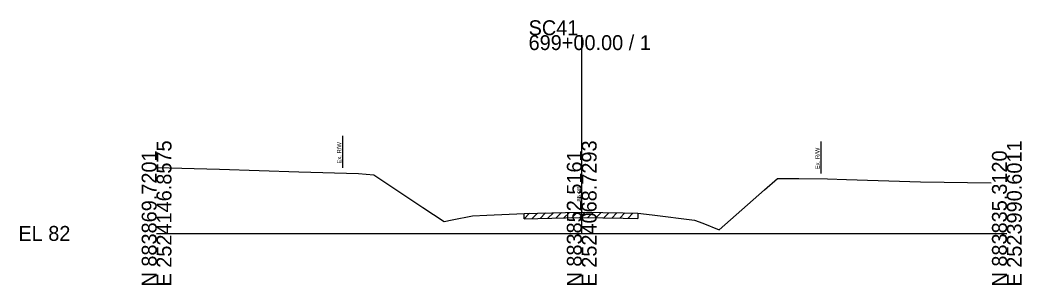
# Model space of a CAD drawing. Extents: x -26 to 183, y -10 to 24021.
# Drawn here: x -25.7 to 162.8, y 21490.3 to 21540.1 of the extents above; entities that cross this region are included whole.
import ezdxf

# ---------------------------------------------------------------- set-up
doc = ezdxf.new("R2010")
doc.units = 0
for name, color, linetype in [('RD_GPK_XS_Cell', 7, 'Continuous'), ('RD_XS_ExGround', 7, 'Continuous'), ('RD_XS_ExPaveRet', 7, 'Continuous'), ('RD_XS_ExRW', 7, 'Continuous'), ('RD_XS_TX_Elev_EX', 7, 'Continuous')]:
    doc.layers.add(name, color=color, linetype=linetype)

msp = doc.modelspace()

# ---------------------------------------------------------------- linework, layer by layer
at = {"layer": 'RD_GPK_XS_Cell'}
for p, q in [((80, 21500), (80, 21537.27)), ((0, 21500), (80, 21500)), ((80, 21500), (160, 21500))]:
    msp.add_line(p, q, dxfattribs=at)
at = {"layer": 'RD_XS_ExGround'}
for p, q in [((0, 21512.42), (11.84, 21512.08)), ((11.84, 21512.08), (26.78, 21511.55)), ((26.78, 21511.55), (37.98, 21511.25)), ((37.98, 21511.25), (40.86, 21511.04)), ((40.86, 21511.04), (50.13, 21504.87)), ((114.38, 21508.18), (116.86, 21510.32)), ((116.86, 21510.32), (120.84, 21510.3)), ((120.84, 21510.3), (126.27, 21510.28)), ((126.27, 21510.28), (129.83, 21510.16)), ((129.83, 21510.16), (143.77, 21509.67)), ((105.85, 21500.69), (114.38, 21508.18)), ((143.77, 21509.67), (157.04, 21509.53)), ((50.13, 21504.87), (54.1, 21502.24)), ((54.1, 21502.24), (55.63, 21502.53)), ((55.63, 21502.53), (59.42, 21503.3)), ((59.42, 21503.3), (62.17, 21503.43)), ((62.17, 21503.43), (69.15, 21503.76)), ((69.15, 21503.76), (76.96, 21503.92)), ((76.96, 21503.92), (80.15, 21503.98)), ((80.15, 21503.98), (87.82, 21503.84)), ((87.82, 21503.84), (90.57, 21503.79)), ((90.57, 21503.79), (93.26, 21503.46)), ((93.26, 21503.46), (101.25, 21502.51)), ((101.25, 21502.51), (102.76, 21501.93)), ((102.76, 21501.93), (105.85, 21500.69))]:
    msp.add_line(p, q, dxfattribs=at)
at = {"layer": 'RD_XS_ExPaveRet'}
for p, q in [((69.15, 21502.76), (70.17, 21503.78)), ((69.15, 21502.76), (69.15, 21503.76)), ((69.15, 21502.76), (76.96, 21502.92)), ((70.65, 21502.79), (71.67, 21503.81)), ((72.15, 21502.82), (73.17, 21503.84)), ((73.65, 21502.85), (74.67, 21503.87)), ((75.15, 21502.88), (76.17, 21503.91)), ((76.65, 21502.92), (77.67, 21503.93)), ((76.96, 21502.92), (80.15, 21502.98)), ((78.15, 21502.94), (79.17, 21503.96)), ((79.65, 21502.97), (80.65, 21503.97)), ((80.15, 21502.98), (87.82, 21502.84)), ((81.15, 21502.96), (82.13, 21503.95)), ((82.65, 21502.94), (83.63, 21503.92)), ((84.15, 21502.91), (85.13, 21503.89)), ((85.65, 21502.88), (86.63, 21503.86)), ((87.15, 21502.86), (88.13, 21503.84)), ((87.82, 21502.84), (90.57, 21502.79)), ((88.65, 21502.83), (89.63, 21503.81)), ((90.57, 21503.79), (90.57, 21502.79))]:
    msp.add_line(p, q, dxfattribs=at)
at = {"layer": 'RD_XS_ExRW'}
for p, q in [((35, 21518.33), (35, 21512.33)), ((125, 21517.28), (125, 21511.28))]:
    msp.add_line(p, q, dxfattribs=at)

# ---------------------------------------------------------------- texts
at = {"layer": 'RD_GPK_XS_Cell'}
for s, p in [('SC41', (70, 21537.27)), ('699+00.00 / 1', (70, 21534.47)), ('EL 82', (-26, 21498.6))]:
    msp.add_text(s, height=2.8, dxfattribs=at).set_placement(p)
for s, p in [('E 2524146.8575', (2.8, 21490)), ('E 2524068.7293', (82.8, 21490)), ('E 2523990.6011', (162.8, 21490)), ('N 883869.7201', (0, 21490)), ('N 883852.5161', (80, 21490)), ('N 883835.3120', (160, 21490))]:
    msp.add_text(s, height=2.8, rotation=90, dxfattribs=at).set_placement(p)
at = {"layer": 'RD_XS_ExRW'}
for p in [(34.75, 21513.12), (124.75, 21512.07)]:
    msp.add_text('Ex. R/W ', height=0.8, rotation=90, dxfattribs=at).set_placement(p)
at = {"layer": 'RD_XS_TX_Elev_EX'}
msp.add_text('85.98', height=0.8, rotation=90, dxfattribs=at).set_placement((79.9, 21505.98))

doc.saveas('drawing.dxf')
